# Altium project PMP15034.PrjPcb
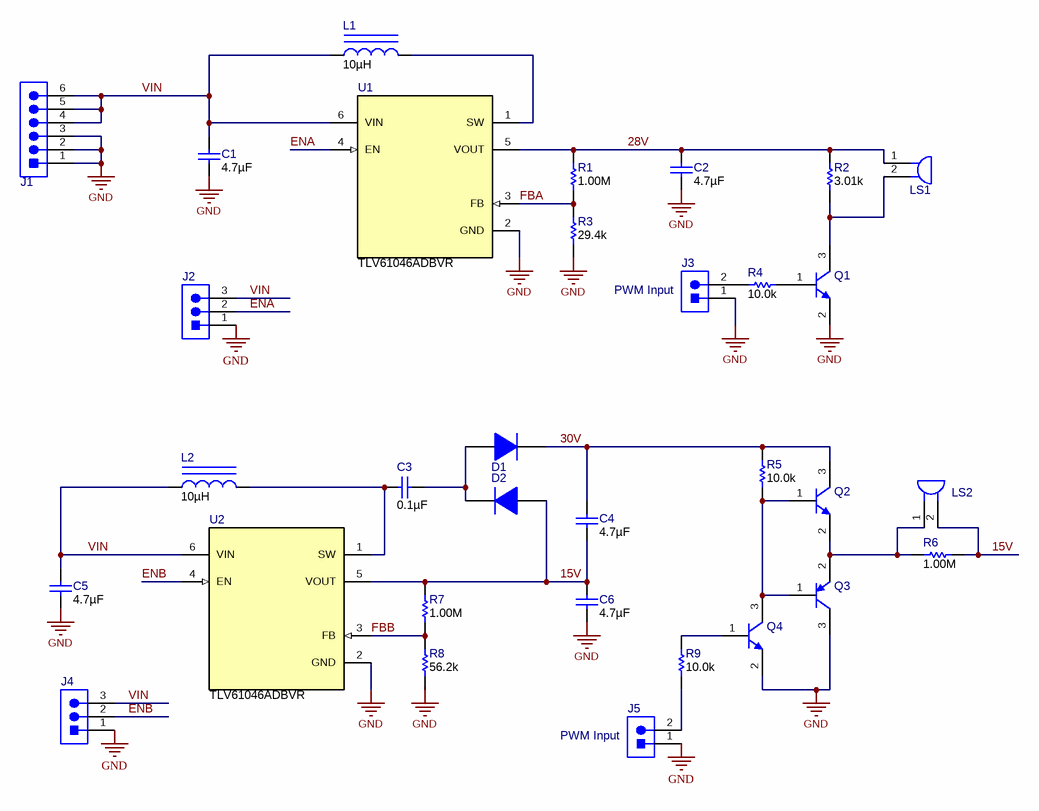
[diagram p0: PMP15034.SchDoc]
TID: N/A; TechSupport: http://www.ti.com/support; SCH_Rev: A; PRJ_Title: Piezoelectric Buzzer Driver Circuit; PRJ_Number: PMP15034; PRJ_Engineer: Jasper Li; PRJ_Customer: Public Release; PCB_Rev: A; PCB_Layout: Jasper Li; CopyrightYear: 2017
1 sheet, 32 parts. Net scope: global (net labels, ports and power ports of the same name join across sheets).
Board file: PMP15034.PcbDoc

## Sheet PMP15034.SchDoc
size A4; Date: Not shown in title block; ApprovedBy: Not shown in title block; CheckedBy: Not shown in title block; Author: Not shown in title block; CompanyName: Not shown in title block; Engineer: Not shown in title block; Organization: Not shown in title block; Address1: Not shown in title block; Address2: Not shown in title block; Address3: Not shown in title block; Address4: Not shown in title block; DocumentNumber: 1; Revision: Use project parameter SCH_Rev; SheetNumber: 2; SheetTotal: 3; PageSetup: Record=PageOptions¦CenterHorizontal=True¦CenterVertical=True¦PrintScale=0.91¦XCorrection=1.00¦YCorrection=1.00¦PrintKind=0¦BorderSize=5000000¦LeftOffset=0¦BottomOffset=0¦Orientation=2¦PaperLength=1000¦PaperWidth=1000¦Scale=100¦PaperSource=15¦PrintQuality=600¦MediaType=1¦DitherType=10¦PrintScaleMode=1¦PaperKind=Letter

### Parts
C1  ValueDisplayed: 4.7µF  [0603]  (hidden comment: GRM188R60J475KE19D)
C2  ValueDisplayed: 4.7µF  [0603]  (hidden comment: GRM188R6YA475KE15D)
C3  ValueDisplayed: 0.1µF  [0603]  (hidden comment: GRM188R71H104KA93D)
C4  ValueDisplayed: 4.7µF  [0603]  (hidden comment: GRM188R6YA475KE15D)
C5  ValueDisplayed: 4.7µF  [0603]  (hidden comment: GRM188R60J475KE19D)
C6  ValueDisplayed: 4.7µF  [0603]  (hidden comment: GRM188R6YA475KE15D)
D1  1N4148W-7-F  [SOD-123]  (value not drawn)
D2  1N4148W-7-F  [SOD-123]  (value not drawn)
J1  TSW-106-07-G-S  [TSW-106-07-G-S]  (value not drawn)
J2  TSW-103-07-G-S  [TSW-103-07-G-S]  (value not drawn)
J3  TSW-102-07-T-S  [Samtec_TSW-102-07-T-S]  (value not drawn)
J4  TSW-103-07-G-S  [TSW-103-07-G-S]  (value not drawn)
J5  TSW-102-07-T-S  [Samtec_TSW-102-07-T-S]  (value not drawn)
L1  ValueDisplayed: 10µH  [FDSD0420]  (hidden comment: FDSD0420-H-100M)
L2  ValueDisplayed: 10µH  [FDSD0420]  (hidden comment: FDSD0420-H-100M)
LS1  PKM13EPYH4002-B0  [MuRata_PKM13]  (value not drawn)
LS2  PKM13EPYH4002-B0  [MuRata_PKM13]  (value not drawn)
Q1  MMBT3904-7-F  [SOT-23]  (value not drawn)
Q2  MMBT3904-7-F  [SOT-23]  (value not drawn)
Q3  MMBT3906-7-F  [SOT-23]  (value not drawn)
Q4  MMBT3904-7-F  [SOT-23]  (value not drawn)
R1  ValueDisplayed: 1.00M  [0603]  (hidden comment: CRCW06031M00FKEA)
R2  ValueDisplayed: 3.01k  [0603]  (hidden comment: CRCW06033K01FKEA)
R3  ValueDisplayed: 29.4k  [0603]  (hidden comment: CRCW060329K4FKEA)
R4  ValueDisplayed: 10.0k  [0603]  (hidden comment: CRCW060310K0FKEA)
R5  ValueDisplayed: 10.0k  [0603]  (hidden comment: CRCW060310K0FKEA)
R6  ValueDisplayed: 1.00M  [0603]  (hidden comment: CRCW06031M00FKEA)
R7  ValueDisplayed: 1.00M  [0603]  (hidden comment: CRCW06031M00FKEA)
R8  ValueDisplayed: 56.2k  [0603]  (hidden comment: CRCW060356K2FKEA)
R9  ValueDisplayed: 10.0k  [0603]  (hidden comment: CRCW060310K0FKEA)
U1  TLV61046ADBVR  [DBV0006A_N]
U2  TLV61046ADBVR  [DBV0006A_N]

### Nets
GND: C1.2 C2.2 C5.2 C6.2 J1.1 J1.2 J1.3 J2.1 J3.1 J4.1 J5.1 Q1.2(E) Q3.3(C) Q4.2(E) R3.1 R8.1 U1.2(GND) U2.2(GND)
15V: C4.2 C6.1 D2.2(A) LS2.2 R6.1 R7.2 U2.5(VOUT)
28V: C2.1 LS1.1 R1.2 R2.2 U1.5(VOUT)
30V: C4.1 D1.1(K) Q2.3(C) R5.1
ENA: J2.2 U1.4(EN)
ENB: J4.2 U2.4(EN)
FBA: R1.1 R3.2 U1.3(FB)
FBB: R7.1 R8.2 U2.3(FB)
VIN: C1.1 C5.1 J1.4 J1.5 J1.6 J2.3 J4.3 L1.1 L2.1 U1.6(VIN) U2.6(VIN)
NetC3_1: C3.1 L2.2 U2.1(SW)
NetC3_2: C3.2 D1.2(A) D2.1(K)
NetJ3_2: J3.2 R4.2
NetJ5_2: J5.2 R9.1
NetL1_2: L1.2 U1.1(SW)
NetLS1_2: LS1.2 Q1.3(C) R2.1
NetLS2_1: LS2.1 Q2.2(E) Q3.2(E) R6.2
NetQ1_1: Q1.1(B) R4.1
NetQ2_1: Q2.1(B) Q3.1(B) Q4.3(C) R5.2
NetQ4_1: Q4.1(B) R9.2

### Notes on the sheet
- PWM Input
- (near J5) PWM Input

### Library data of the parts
C1 C5 = GRM188R60J475KE19D: CAP, CERM, 4.7 µF, 6.3 V, +/- 10%, X5R, 0603; Manufacturer: MuRata; Polarized: N; CompType: Capacitor; Value: 4.7uF; U/M: EA; Cap_F: 0.0000047; Tolerance_%: 10; ESR_ohm: 0.005; Value1: 0.005 ohm; VDC_V: 6.3; Value2: 6.3V; IRMS_A: 2; TaMin_C: -55; TaMax_C: 85; AEC Category: Q200; SizeArea_mm2: 1.28; SizeAreaWB_mm2: 4.68; SizeX_mm: 1.6; SizeY_mm: 0.8; SizeZ_mm: 1
C2 C4 C6 = GRM188R6YA475KE15D: CAP, CERM, 4.7 µF, 35 V, +/- 10%, X5R, 0603; Manufacturer: MuRata; Polarized: N; CompType: Capacitor; Value: 4.7uF; U/M: EA; Cap_F: 0.0000047; Tolerance_%: 10; Value1: Unknown; VDC_V: 35; Value2: 35V; TaMin_C: -55; TaMax_C: 85; AEC Category: Q200; SizeArea_mm2: 1.28; SizeAreaWB_mm2: 4.68; SizeX_mm: 1.6; SizeY_mm: 0.8; SizeZ_mm: 1
C3 = GRM188R71H104KA93D: CAP, CERM, 0.1 µF, 50 V, +/- 10%, X7R, 0603; Manufacturer: MuRata; Polarized: N; CompType: Capacitor; Value: 0.1uF; U/M: EA; Cap_F: 0.0000001; Tolerance_%: 10; Value1: Unknown; VDC_V: 50; Value2: 50V; TaMin_C: -55; TaMax_C: 125; AEC Category: Q200; SizeArea_mm2: 1.28; SizeAreaWB_mm2: 4.68; SizeX_mm: 1.6; SizeY_mm: 0.8; SizeZ_mm: 1
D1 D2 = 1N4148W-7-F: Diode, Ultrafast, 100 V, 0.15 A, SOD-123; Manufacturer: Diodes Inc.; U/M: EA; Vf_V: 1.25; Value: 100V; Value1: 0.15A; Value2: 1.25V; Io_A: 0.15; Vr_V: 100; TJmax_C: 150; SizeAreaWB_mm2: 13.095; SizeArea_mm2: 6.545; SizeX_mm: 3.85; SizeY_mm: 1.7; SizeZ_mm: 1.35; AEC Category: Q101
J1 = TSW-106-07-G-S: Header, 100mil, 6x1, Gold, TH; Manufacturer: Samtec; SymbolCreator: a0412235; Pitch_mm: 2.54; Gender: Male; Shrouded: N; Row_Count: 1; Current_A: 6.3; Voltage_V: 550; Cert_CSA: Y
J2 J4 = TSW-103-07-G-S: Header, 100mil, 3x1, Gold, TH; Manufacturer: Samtec; SymbolCreator: a0799628; U/M: EA
J3 J5 = TSW-102-07-T-S: Header, 2.54 mm, 2x1, Tin, TH; Manufacturer: Samtec; SymbolCreator: a0412235; Pitch_mm: 2.54; Gender: Male; Shrouded: N; Row_Count: 1; Current_A: 6.3; Voltage_V: 550; Cert_CSA: Y
L1 L2 = FDSD0420-H-100M: Inductor, Shielded, Powdered Iron, 10 µH, 2 A, 0.2 ohm, SMD; Manufacturer: MuRata Toko; Value: 10uH; Ind_H: 10.0E-6; Imax_A: 2; Irms: 2A @ 40C rise; Isat: 3.3A @ 30% inductance drop; DCR_ohm: 0.2; Value1: 0.2 ohm; Value2: 2A; SizeAreaWB_mm2: 27.04; SizeArea_mm2: 17.64; SizeX_mm: 4.2; AEC Category: Q200
LS1 LS2 = PKM13EPYH4002-B0: Buzzer, 4 kHz, 12.6mm Dia, TH; Manufacturer: MuRata; SymbolCreator: a0411947; Value: 4kHz; SizeAreaWB_mm2: 213.16; SizeArea_mm2: 158.76; SizeX_mm: 12.6; SizeZ_mm: 7.4
Q1 Q2 Q4 = MMBT3904-7-F, Diodes Inc.: Transistor, NPN, 40 V, 0.2 A, SOT-23; CompType: BJT; PNP: 0; NPN: 1; Vceo_V: 40; Vcesat1_V: 0.2; Value: 40 V; Value1: 0.2 A; HfeMax: 400; TaMin_C: -55; TaMax_C: 150; SizeAreaWB_mm2: 14; SizeArea_mm2: 7.5; SizeX_mm: 2.5; SizeY_mm: 3; SizeZ_mm: 1.1; U/M: EA; AEC Category: Q101
Q3 = MMBT3906-7-F, Diodes Inc.: Transistor, PNP, 40 V, 0.2 A, SOT-23; CompType: BJT; PNP: 1; NPN: 0; Vceo_V: 40; Vcesat1_V: 0.25; Value: 40 V; IcRated_A: 0.2; Value1: 0.2 A; HfeMax: 400; TaMin_C: -55; TaMax_C: 150; SizeAreaWB_mm2: 14; SizeArea_mm2: 7.5; SizeX_mm: 2.5; SizeY_mm: 3; SizeZ_mm: 1.1; U/M: EA; AEC Category: Q101
R1 R6 R7 = CRCW06031M00FKEA: RES, 1.00 M, 1%, 0.1 W, 0603; Manufacturer: Vishay-Dale; CompType: Resistor; Value: 1.00Meg; Res_ohm: 1000000; Value_Code: 1M00; Tolerance_%: 1; Power_W: 0.1; Value2: 0.1W; VDC_V: 75; TempCo: 100 ppm/C; SizeArea_mm2: 1.28; SizeX_mm: 1.6; SizeY_mm: 0.8; EIA_Code: E96; U/M: EA; AEC Category: Q200
R2 = CRCW06033K01FKEA: RES, 3.01 k, 1%, 0.1 W, 0603; Manufacturer: Vishay-Dale; CompType: Resistor; Value: 3.01k; Res_ohm: 3010; Value_Code: 3k01; Tolerance_%: 1; Power_W: 0.1; Value2: 0.1W; VDC_V: 75; TempCo: 100 ppm/C; SizeArea_mm2: 1.28; SizeX_mm: 1.6; SizeY_mm: 0.8; EIA_Code: E96; U/M: EA; AEC Category: Q200; Green_Lifecycle: Active; Green_REACh: Passed
R3 = CRCW060329K4FKEA: RES, 29.4 k, 1%, 0.1 W, 0603; Manufacturer: Vishay-Dale; CompType: Resistor; Value: 29.4k; Res_ohm: 29400; Value_Code: 29k4; Tolerance_%: 1; Power_W: 0.1; Value2: 0.1W; VDC_V: 75; TempCo: 100 ppm/C; SizeArea_mm2: 1.28; SizeX_mm: 1.6; SizeY_mm: 0.8; EIA_Code: E96; U/M: EA; AEC Category: Q200
R4 R5 R9 = CRCW060310K0FKEA: RES, 10.0 k, 1%, 0.1 W, 0603; Manufacturer: Vishay-Dale; CompType: Resistor; Value: 10.0k; Res_ohm: 10000; Value_Code: 10k0; Tolerance_%: 1; Power_W: 0.1; Value2: 0.1W; VDC_V: 75; TempCo: 100 ppm/C; SizeArea_mm2: 1.28; SizeX_mm: 1.6; SizeY_mm: 0.8; EIA_Code: E96; U/M: EA; AEC Category: Q200
R8 = CRCW060356K2FKEA: RES, 56.2 k, 1%, 0.1 W, 0603; Manufacturer: Vishay-Dale; CompType: Resistor; Value: 56.2k; Res_ohm: 56200; Value_Code: 56k2; Tolerance_%: 1; Power_W: 0.1; Value2: 0.1W; VDC_V: 75; TempCo: 100 ppm/C; SizeArea_mm2: 1.28; SizeX_mm: 1.6; SizeY_mm: 0.8; EIA_Code: E96; U/M: EA; AEC Category: Q200; Green_Lifecycle: Active; Green_REACh: Passed
U1 U2 = TLV61046ADBVR: 28-V Output Voltage Boost Converter with Power Diode and Isolation Switch, DBV0006A (SOT-6); Alternate PartNumber: TLV61046ADBVT; Manufacturer: Texas Instruments; SymbolCreator: a0411947; SizeArea_mm2: 8.12; SizeAreaWB_mm2: 14.82; SizeX_mm: 2.8; SizeY_mm: 2.9; SizeZ_mm: 1.45; CompType: IC; U/M: EA

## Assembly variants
001: not fitted FID1 FID2 FID3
